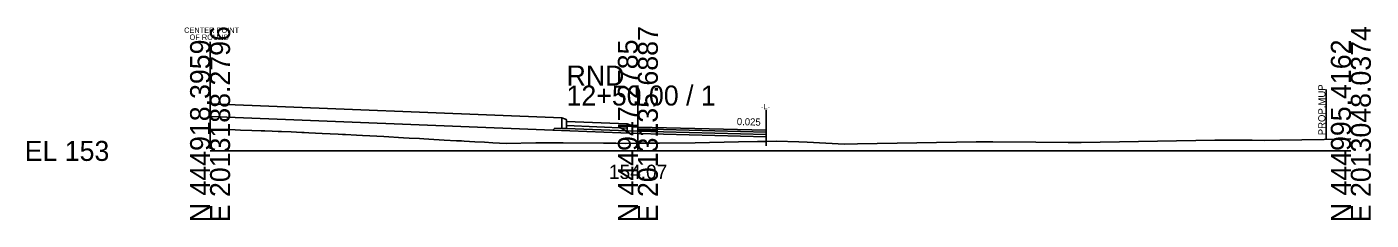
# Model space of a CAD drawing. Extents: x -26 to 163, y -10 to 7518.
# Drawn here: x -25.7 to 162.8, y 4990.3 to 5017.4 of the extents above; entities that cross this region are included whole.
import ezdxf

# ---------------------------------------------------------------- set-up
doc = ezdxf.new("R2010")
doc.units = 0
for name, color, linetype in [('Exist Cross Section Cell', 7, 'Continuous'), ('Exist XS Center Line Elevation Label', 7, 'Continuous'), ('Exist XS Ground Line', 7, 'Continuous'), ('Prop CMT Conc Surface', 7, 'Continuous'), ('Prop CMT Concrete Structures', 7, 'Continuous'), ('Prop CMT Pvmt Course 1', 7, 'Continuous'), ('Prop CMT Pvmt Course 1 CG', 7, 'Continuous'), ('Prop CMT Pvmt Course 2', 7, 'Continuous'), ('Prop CMT Pvmt Course 3', 7, 'Continuous'), ('Prop CMT Pvmt Surface', 7, 'Continuous'), ('Prop CMT Shear Line', 7, 'Continuous'), ('Prop CMT Shear Line Text', 7, 'Continuous'), ('Prop CMT Slope Grass', 7, 'Continuous'), ('Prop CMT Subgrade Earthwork', 7, 'Continuous'), ('Prop XS Earthwork Shape', 7, 'Continuous'), ('Prop XS Label Text', 7, 'Continuous'), ('Prop XS SE Text', 7, 'Continuous')]:
    doc.layers.add(name, color=color, linetype=linetype)

msp = doc.modelspace()

# ---------------------------------------------------------------- linework, layer by layer
at = {"layer": 'Exist Cross Section Cell'}
for p, q in [((60, 5000), (60, 5009.16)), ((0, 5000), (60, 5000)), ((60, 5000), (160, 5000))]:
    msp.add_line(p, q, dxfattribs=at)
at = {"layer": 'Exist XS Ground Line'}
msp.add_lwpolyline([(0, 5003.05), (1.43, 5003.01), (2.16, 5002.99), (3.5, 5002.95), (4.29, 5002.92), (5.86, 5002.86), (7.16, 5002.81), (7.7, 5002.79), (8.7, 5002.75), (9.54, 5002.72), (10.01, 5002.7), (11.38, 5002.65), (12.86, 5002.59), (13.21, 5002.57), (13.86, 5002.55), (15.7, 5002.45), (17.98, 5002.33), (18.55, 5002.3), (19.01, 5002.28), (20.55, 5002.19), (21.4, 5002.15), (22.39, 5002.1), (24.35, 5002), (27.12, 5001.85), (27.93, 5001.8), (29.39, 5001.72), (29.98, 5001.68), (30.69, 5001.64), (32.82, 5001.52), (34.58, 5001.43), (35.28, 5001.39), (35.65, 5001.37), (37.14, 5001.28), (38.51, 5001.21), (39.68, 5001.15), (41.52, 5001.03), (45.68, 5001.12), (49.5, 5001.13), (55.17, 5001.07), (56.93, 5001.07), (58.29, 5001.06), (60, 5001.07), (63.05, 5001.07), (68.04, 5001.14), (74.11, 5001.28), (79.45, 5001.35), (82.58, 5001.29), (83.73, 5001.24), (88.98, 5000.95), (90.79, 5000.97), (107.45, 5001.26), (108.15, 5001.26), (109.77, 5001.25), (115.8, 5001.22), (120.37, 5001.2), (121.62, 5001.2), (122.18, 5001.2), (140.91, 5001.49), (146.15, 5001.49), (147.91, 5001.48), (150.05, 5001.51), (159.32, 5001.66), (160, 5001.67)], dxfattribs=at)
at = {"layer": 'Prop CMT Conc Surface'}
for points in [[(50, 5004.31), (49.96, 5004.41), (49.85, 5004.45), (49.34, 5004.64)], [(50, 5004.14), (50, 5004.31)], [(60, 5003.34), (59.25, 5003.36), (59.25, 5003.53), (58.5, 5003.78)]]:
    msp.add_lwpolyline(points, dxfattribs=at)
at = {"layer": 'Prop CMT Concrete Structures'}
for points in [[(50, 5004.31), (49.96, 5004.41), (49.85, 5004.45), (49.34, 5004.64)], [(49.34, 5004.64), (49.34, 5003.14)], [(50, 5004.14), (50, 5004.31)], [(50, 5003.14), (50, 5004.14)], [(50, 5004.14), (50, 5003.56)], [(58.5, 5003.78), (50, 5004.12)], [(60, 5003.34), (59.25, 5003.36), (59.25, 5003.53), (58.5, 5003.78)], [(58.5, 5003.78), (58.5, 5002.8)], [(58.5, 5003.2), (58.5, 5003.78)], [(49.34, 5003.14), (50, 5003.14)], [(50, 5003.54), (58.5, 5003.2)], [(58.5, 5002.8), (60, 5002.76)], [(60, 5002.76), (60, 5003.34)]]:
    msp.add_lwpolyline(points, dxfattribs=at)
at = {"layer": 'Prop CMT Pvmt Course 1'}
for points in [[(60, 5003.34), (78, 5002.89)], [(60, 5003.09), (60, 5003.34)], [(78, 5002.64), (60, 5003.09)], [(78, 5002.89), (78, 5002.64)]]:
    msp.add_lwpolyline(points, dxfattribs=at)
msp.add_lwpolyline([(60, 5003.09), (60, 5003.22), (60, 5003.22), (60, 5003.09)], close=True, dxfattribs=at)
at = {"layer": 'Prop CMT Pvmt Course 1 CG'}
for points in [[(60, 5002.43), (60, 5002.76)], [(78, 5001.97), (78, 5002.31)]]:
    msp.add_lwpolyline(points, dxfattribs=at)
at = {"layer": 'Prop CMT Pvmt Course 2'}
for points in [[(60, 5002.76), (60, 5003.09)], [(60, 5003.09), (78, 5002.64)], [(78, 5002.31), (60, 5002.76)], [(78, 5002.64), (78, 5002.31)]]:
    msp.add_lwpolyline(points, dxfattribs=at)
at = {"layer": 'Prop CMT Pvmt Course 3'}
for points in [[(50, 5003.14), (58.5, 5002.8)], [(60, 5002.76), (78, 5002.31)], [(60, 5002.43), (60, 5002.76)], [(78, 5001.97), (60, 5002.43)], [(78, 5002.31), (78, 5001.97)]]:
    msp.add_lwpolyline(points, dxfattribs=at)
at = {"layer": 'Prop CMT Pvmt Surface'}
msp.add_lwpolyline([(60, 5003.34), (78, 5002.89)], dxfattribs=at)
at = {"layer": 'Prop CMT Shear Line'}
for p, q in [((0, 5000.28), (0, 5015.28)), ((78, 5000.72), (78, 5005.73))]:
    msp.add_line(p, q, dxfattribs=at)
at = {"layer": 'Prop CMT Slope Grass'}
for p, q in [((49.34, 5004.62), (0, 5006.59)), ((48.06, 5002.91), (0, 5004.83))]:
    msp.add_line(p, q, dxfattribs=at)
at = {"layer": 'Prop CMT Subgrade Earthwork'}
for p, q in [((0, 5006.59), (0, 5003.05)), ((48.34, 5003.18), (48.06, 5002.91)), ((78, 5002.89), (78, 5001.97)), ((78, 5001.97), (78, 5001.33))]:
    msp.add_line(p, q, dxfattribs=at)
for points in [[(48.06, 5002.91), (60, 5002.43)], [(48.34, 5003.18), (49.34, 5003.14)], [(60, 5002.43), (78, 5001.97)]]:
    msp.add_lwpolyline(points, dxfattribs=at)
at = {"layer": 'Prop XS Earthwork Shape'}
msp.add_lwpolyline([(13.86, 5002.55), (15.7, 5002.45), (17.98, 5002.33), (18.55, 5002.3), (19.01, 5002.28), (20.55, 5002.19), (21.4, 5002.15), (22.39, 5002.1), (24.35, 5002), (27.12, 5001.85), (27.93, 5001.8), (29.39, 5001.72), (29.98, 5001.68), (30.69, 5001.64), (32.82, 5001.52), (34.58, 5001.43), (35.28, 5001.39), (35.65, 5001.37), (37.14, 5001.28), (38.51, 5001.21), (39.68, 5001.15), (41.52, 5001.03), (45.68, 5001.12), (49.5, 5001.13), (55.17, 5001.07), (56.93, 5001.07), (58.29, 5001.06), (60, 5001.07), (63.05, 5001.07), (68.04, 5001.14), (74.11, 5001.28), (78, 5001.33), (78, 5001.97), (60, 5002.43), (48.06, 5002.91), (0, 5004.83), (0, 5003.05), (1.43, 5003.01), (2.16, 5002.99), (3.5, 5002.95), (4.29, 5002.92), (5.86, 5002.86), (7.16, 5002.81), (7.7, 5002.79), (8.7, 5002.75), (9.54, 5002.72), (10.01, 5002.7), (11.38, 5002.65), (12.86, 5002.59), (13.21, 5002.57)], close=True, dxfattribs=at)
at = {"layer": 'Prop XS Label Text'}
msp.add_line((156.52, 5008.61), (156.52, 5001.61), dxfattribs=at)

# ---------------------------------------------------------------- texts
at = {"layer": 'Exist Cross Section Cell'}
for s, p in [('E 2013188.2796', (2.8, 4990)), ('E 2013135.6887', (62.8, 4990)), ('E 2013048.0374', (162.8, 4990)), ('N 444918.3959', (0, 4990)), ('N 444947.2785', (60, 4990)), ('N 444995.4162', (160, 4990))]:
    msp.add_text(s, height=2.8, rotation=90, dxfattribs=at).set_placement(p)
for s, p in [('RND', (50, 5009.16)), ('12+50.00 / 1', (50, 5006.36)), ('EL 153', (-26, 4998.6))]:
    msp.add_text(s, height=2.8, dxfattribs=at).set_placement(p)
at = {"layer": 'Exist XS Center Line Elevation Label'}
msp.add_text('154.07', height=2, dxfattribs=at).set_placement((55.94, 4996.07))
at = {"layer": 'Prop CMT Shear Line Text'}
for s, p in [('CENTER POINT', (-3.64, 5016.54)), ('OF ROUND', (-2.88, 5015.56)), ('-L-', (77.27, 5005.84))]:
    msp.add_text(s, height=0.75, dxfattribs=at).set_placement(p)
at = {"layer": 'Prop XS Label Text'}
msp.add_text('PROP.MUP', height=1, rotation=90, dxfattribs=at).set_placement((156.42, 5002.19))
at = {"layer": 'Prop XS SE Text'}
msp.add_text('0.025', height=1, rotation=358.5613, dxfattribs=at).set_placement((73.87, 5003.62))

doc.saveas('drawing.dxf')
